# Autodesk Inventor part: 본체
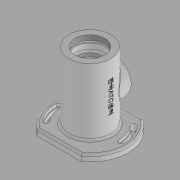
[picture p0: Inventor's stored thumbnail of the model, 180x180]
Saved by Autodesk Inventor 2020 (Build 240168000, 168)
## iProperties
Created: 2022-05
Part Number: 본체
Material: 일반
Document SubType Name: Modeling
Designer: User
Density: 1 g/cm^3
Appearance: 기본값
Mass: 254.11 g
Surface Area: 619.464 cm^2
Volume: 254.11 cm^3
Author: User
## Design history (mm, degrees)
sketch "스케치1"
  geometry: L1 (33.985, -47)-(-33.985, -47); L2 (-33.985, -47)-(-33.985, 47); L3 (-33.985, 47)-(33.985, 47); L4 (33.985, 47)-(33.985, -47); L5 (33.985, -47)-(-33.985, 47); L6 (-33.985, -47)-(33.985, 47); C1 r 48 at (0, 0); A1 r 58 centre (0, 0) between (-33.985, 47) and (-33.985, -47); A2 r 58 centre (0, 0) between (33.985, -47) and (33.985, 47); 2 further points
  constraints: 12 end point, 4 point on circle, 3 centre point, 3 midpoint, 2 coincident, 2 parallel, 1 horizontal, 1 perpendicular
  dimensions: "d1" = 94 distance between parallel lines of L1 L3; "d2" = 58 radius of A1; "d3" = 96 diameter of C1; "d4" = 58 radius of A2
extrude "돌출1" new body sketch "스케치1" distance "d6" = 10; taper "d7" = 0 deg
sketch "스케치2"
  geometry: L1 (47, 0)-(-47, 0) reference; L2 (-47, 0)-(-47, 10) reference; L3 (47, 10)-(-47, 10) reference; L4 (47, 0)-(47, 10) reference; L5 (32, 10)-(32, 112); L6 (32, 112)-(0, 112); L7 (0, 112)-(0, 10); L8 (22.5, 112)-(22.5, 104); L9 (22.5, 104)-(24, 104); L10 (24, 104)-(24, 101); L11 (24, 101)-(22.5, 101); L12 (18.5, 87.75)-(18.5, 86); L13 (18.5, 86)-(17.5, 86); L14 (17.5, 86)-(17.5, 75); L15 (17.5, 75)-(27, 75); L16 (27, 75)-(27, 37); L17 (27, 37)-(17.5, 37); L18 (17.5, 37)-(17.5, 26); L19 (17.5, 26)-(15, 26); L20 (15, 26)-(15, 21); L21 (15, 21)-(11, 21); L22 (11, 21)-(11, 18.3); L23 (11, 18.3)-(15, 18.3); L24 (15, 18.3)-(15, 11); L25 (15, 11)-(20, 11); L26 (22.5, 101)-(22.5, 90); L27 (22.5, 90)-(20.91, 90); L28 (18.5, 87.75)-(17.5, 87.75); L29 (17.5, 87.75)-(17.5, 90); L30 (17.5, 90)-(20.91, 90); L31 (36, 0)-(36, -3); L32 (36, -3)-(0, -3); L33 (0, -3)-(0, 10); L34 (20, 11)-(30, -3); 3 further points
  constraints: 60 end point, 19 perpendicular, 6 point on line, 5 vertical, 2 horizontal, 1 collinear, 1 midpoint
  dimensions: "d8" = 102 distance of L5.start L5.end; "d9" = 64 diameter of L5 L7; "d10" = 48 diameter of L10 L7; "d13" = 30 diameter of L24.end L7; "d15" = 40 diameter of L25.end L7; "d16" = 22 diameter of L22 L7; "d17" = 30 diameter of L20 L7; "d18" = 35 diameter of L18 L7; "d19" = 54 diameter of L16 L7; "d20" = 37 diameter of L12 L7; "d21" = 45 diameter of L8 L7; "d22" = 45 diameter of L26 L7; "d23" = 8 distance of L8.start L8.end; "d25" = 3 distance of L9.end L10.end; "d26" = 22 distance of L8.start L26.end; "d29" = 60 diameter of L34.end L33; "d30" = 14 vertical distance of L34.end L25.end; "d31" = 3 distance of L31.start L31.end; "d32" = 72 diameter of L31 L33; "d33" = 29 distance from line of L19.end L32; "d34" = 7.3 distance of L23.end L24.end; "d35" = 5 distance of L19.end L20.end; "d36" = 11 distance of L17.end L18.end; "d37" = 38 distance of L15.end L16.end; "d38" = 11 distance of L13.end L14.end; "d39" = 1.75 distance of L12.start L12.end
  node "투영된 루프1"
revolve "회전1" stored, may be unused: angle "d40" = 90 deg
revolve "회전2" stored, may be unused: angle "d41" = 90 deg
node "작업 평면1"
sketch "스케치3"
  geometry: L1 (-32, 112)-(32, 112) reference; C1 r 25 at (0, 56); 2 further points
  constraints: 1 centre point, 1 midpoint, 1 vertical alignment
  dimensions: "d43" = 50 diameter of C1; "d44" = 56 distance from line of C1.centre L1
extrude "돌출2" join sketch "스케치3" stored distance "d45" = 10; taper "d46" = 5 deg
sketch "스케치5"
  geometry: C1 r 25 at (0, 0) reference; 2 further points
  constraints: 1 coincident
hole "구멍1" sketch "스케치5" at (0, 0) diameter "d47" = 32; stored, may be unused: countersink angle "d51" = 90 deg, drill point angle "d53" = 118 deg; dims "d48" = 8, "d49" = 4, "d50" = 2, "d52" = 10
sketch "스케치6"
  geometry: L1 (33.985, 47)-(-33.985, 47) reference; L2 (-33.985, -47)-(33.985, -47) reference; L3 (0, 0)-(112.552, 0); L4 (0, 0)-(-121.773, 0); L5 (0, 0)-(-77.894, -65.361); L6 (0, 0)-(-52.034, 62.012); L7 (0, 0)-(70.035, 58.766); C1 r 30 at (0, 0) reference; C2 r 4 at (36.77, 30.854); C3 r 4 at (-36.77, -30.854); A1 r 58 centre (0, 0) between (-33.985, 47) and (-33.985, -47) reference; A2 r 58 centre (0, 0) between (33.985, -47) and (33.985, 47) reference; A3 r 48 centre (0, 0) between (-48, 0) and (-36.77, -30.854); A4 r 52 centre (0, 0) between (-52, 0) and (-39.834, -33.425); A5 r 44 centre (0, 0) between (-44, 0) and (-33.706, -28.283); A6 r 4 centre (-48, 0) between (-44, 0) and (-52, 0); A7 r 4 centre (-36.77, -30.854) between (-39.834, -33.425) and (-33.706, -28.283); A8 r 48 centre (0, 0) between (36.77, 30.854) and (-36.77, -30.854); A9 r 45.75 centre (0, 0) between (-45.75, 0) and (-35.047, -29.408); A10 r 2.25 centre (-48, 0) between (-45.75, 0) and (-50.25, 0); A11 r 50.25 centre (0, 0) between (-50.25, 0) and (-38.494, -32.3); A12 r 2.25 centre (-36.77, -30.854) between (-38.494, -32.3) and (-35.047, -29.408); A13 r 48 centre (0, 0) between (48, 0) and (36.77, 30.854); A14 r 52 centre (0, 0) between (52, 0) and (39.834, 33.425); A15 r 44 centre (0, 0) between (44, 0) and (33.706, 28.283); A16 r 4 centre (48, 0) between (44, 0) and (52, 0); A17 r 4 centre (36.77, 30.854) between (39.834, 33.425) and (33.706, 28.283); A18 r 50.25 centre (0, 0) between (50.25, 0) and (38.494, 32.3); A19 r 2.25 centre (48, 0) between (45.75, 0) and (50.25, 0); A20 r 45.75 centre (0, 0) between (45.75, 0) and (35.047, 29.408); A21 r 2.25 centre (36.77, 30.854) between (38.494, 32.3) and (35.047, 29.408); 9 further points
  constraints: 38 point on circle, 21 centre point, 10 end point, 8 tangent, 5 point on line, 4 coincident, 1 horizontal, 1 parallel, 6 other
  dimensions: "d54" = 48 radius of A3; "d55" = 96 diameter of A8; "d56" = 40 deg angle of L5 L4; "d58" = 8 radial gap between concentric circles of A4 A5; "d59" = 4.5 radial gap between concentric circles of A9 A11; "d60" = 90 deg angle of L5 L6; "d62" = 40 deg angle of L3 L7; "d63" = 8 radial gap between concentric circles of A14 A15; "d64" = 4.5 radial gap between concentric circles of A18 A20; "d70" = 8 diameter of C2; "d71" = 8 diameter of C3
extrude "돌출3" cut sketch "스케치6" extent not by distance; stored distance "d65" = 0; taper "d66" = 0 deg
extrude "돌출4" cut sketch "스케치6" distance "d67" = 4.4; taper "d68" = 0 deg
extrude "돌출5" cut sketch "스케치6" extent not by distance; stored distance "d72" = 0; taper "d73" = 0 deg
sketch "스케치7" dims "d74" = 41
  geometry: C1 r 25 at (0, 0) reference; 3 further points
  constraints: 2 horizontal alignment, 1 coincident, 2 other
hole "구멍2" sketch "스케치7" at (-20.5, 0) diameter "d75" = 2.62111; stored, may be unused: countersink angle "d79" = 90 deg, drill point angle "d81" = 118 deg; dims "d76" = 6, "d77" = 4, "d78" = 2, "d80" = 8
node "작업 평면3"
sketch "스케치8"
  geometry: L1 (-32, 51)-(32, 51) reference; L2 (47, -61)-(-47, -61) reference; 3 further points
  constraints: 1 midpoint, 1 vertical alignment, 1 other
  dimensions: "d86" = 62 distance from line of L2 point (0, 1)
feature "엠보싱1" sketch "스케치8" dims "d1" = 94, "d2" = 58, "d4" = 58, "d87" = 0.5, "d88" = 0
fillet "모깎기1" dims "d89" = 3
fillet "모깎기2" dims "d90" = 3
fillet "모깎기3" dims "d91" = 3
feature "스레드1" dims "d92" = 8, "d93" = 0
chamfer "모따기1" distance "d95" = 1; stored, may be unused: second distance "d96" = 2, angle "d97" = 45 deg
chamfer "모따기2" distance "d99" = 0.7; stored, may be unused: second distance "d100" = 2, angle "d101" = 30 deg
fillet "모깎기6" dims "d102" = 0.5
fillet "모깎기7" dims "d103" = 0.6
chamfer "모따기3" distance "d104" = 1; stored, may be unused: second distance "d105" = 2, angle "d106" = 30 deg
chamfer "모따기4" distance "d107" = 1; stored, may be unused: second distance "d108" = 2, angle "d109" = 30 deg
node "솔리드1"
pattern_circular "원형 패턴1" dims angle "d83" = 360 deg
feature "A9D066F2-1C7D-4E18-AEED-F7BC21143FA4" dims "d92" = 8, "d93" = 0
other parameters: "d42" = 38
